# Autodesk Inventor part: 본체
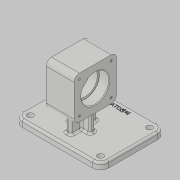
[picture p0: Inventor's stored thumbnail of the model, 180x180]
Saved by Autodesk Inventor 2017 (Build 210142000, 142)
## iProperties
Part Number: 본체
Material: 일반
Document SubType Name: Modeling
Designer: mrc
Density: 1 g/cm^3
Appearance: 기본값
Author: mrc
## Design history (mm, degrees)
sketch "스케치1"
  geometry: L1 (65, -49)-(-65, -49); L2 (-65, -49)-(-65, 49); L3 (-65, 49)-(65, 49); L4 (65, 49)-(65, -49); L5 (65, -49)-(-65, 49); L6 (-65, -49)-(65, 49); 1 further point
  constraints: 12 end point, 2 midpoint, 2 parallel, 1 horizontal, 1 perpendicular
  dimensions: "d1" = 130 distance of L2.end L3.end; "d2" = 98 distance of L1.end L2.end
extrude "돌출1" new body sketch "스케치1" distance "d3" = 10; taper "d4" = 0 deg
sketch "스케치7"
  geometry: L1 (0, -49)-(0, 49) reference; L2 (0, -49)-(10, -49) reference; L3 (10, 49)-(10, -49) reference; L4 (0, 49)-(10, 49) reference; L5 (0, -49)-(0, 13); L6 (0, 13)-(70, 13); L7 (38, -19)-(102, -19); L8 (102, -19)-(102, 45); L9 (102, 45)-(38, 45); L10 (38, 45)-(38, -19); L11 (38, -19)-(102, 45); L12 (102, -19)-(38, 45); 1 further point
  constraints: 16 end point, 2 midpoint, 2 parallel, 2 perpendicular, 1 horizontal, 1 point on line
  dimensions: "d21" = 62 distance of L1.start L5.end; "d22" = 70 distance of L5.end L6.end; "d23" = 64 distance of L9.end L8.end; "d24" = 64 distance of L8.end L7.end
extrude "돌출3" join sketch "스케치7" stored distance "d25" = 42; taper "d26" = 0 deg
sketch "스케치8"
  geometry: L1 (49, 10)-(49, 0) reference; L2 (49, 0)-(-49, 0) reference; L3 (-49, 0)-(-49, 10) reference; L4 (-49, 10)-(49, 10) reference; L5 (19, 38)-(-45, 38) reference; L6 (-45, 38)-(-45, 102) reference; L7 (-45, 102)-(19, 102) reference; L8 (19, 102)-(19, 38) reference; L9 (19, 38)-(19, 102) reference; L10 (19, 102)-(-45, 102) reference; L11 (-45, 102)-(-45, 38) reference; L12 (-45, 38)-(19, 38) reference; C1 r 20.523 at (-13, 70); 1 further point
  constraints: 1 centre point
hole "구멍2" sketch "스케치8" at (-13, 70) diameter "d27" = 36; stored, may be unused: countersink angle "d31" = 90 deg, drill point angle "d33" = 118 deg; dims "d28" = 6, "d29" = 42, "d30" = 15, "d32" = 8
sketch "스케치9"
  geometry: L1 (19, 38)-(19, 102) reference; L2 (19, 102)-(-45, 102) reference; L3 (-45, 102)-(-45, 38) reference; L4 (-45, 38)-(19, 38) reference; L5 (-13, 70)-(-13, 94); L6 (-13, 94)-(-37, 94); C1 r 21 at (-13, 70) reference; C2 r 4.148 at (-37, 94); 1 further point
  constraints: 4 end point, 1 centre point, 1 coincident, 1 perpendicular, 1 vertical
  dimensions: "d34" = 24 distance of L5.start L5.end; "d35" = 24 distance of L5.end L6.end
hole "구멍3" sketch "스케치9" at (-37, 94) diameter "d36" = 3.242; stored, may be unused: countersink angle "d40" = 90 deg, drill point angle "d42" = 118 deg; dims "d37" = 8, "d38" = 42, "d39" = 15, "d41" = 10
fillet "모깎기1" dims "d55" = 8
sketch "스케치11"
  geometry: L1 (4, -33)-(-4, -33); L2 (-4, -33)-(-4, 7); L3 (-4, 7)-(4, 7); L4 (4, 7)-(4, -33); L5 (4, -33)-(-4, 7); L6 (-4, -33)-(4, 7); L7 (17, -17)-(-17, -17); L8 (-17, -17)-(-17, -9); L9 (-17, -9)-(17, -9); L10 (17, -9)-(17, -17); L11 (17, -17)-(-17, -9); L12 (-17, -17)-(17, -9); L13 (65, 49)-(65, -49) reference; L14 (-65, 49)-(65, 49) reference; 3 further points
  constraints: 24 end point, 5 midpoint, 4 parallel, 2 horizontal, 2 perpendicular
  dimensions: "d73" = 34 distance of L8.end L9.end; "d74" = 40 distance of L3.end L1.start; "d75" = 65 distance from line of L13 point (0, -13); "d76" = 62 distance from line of point (0, -13) L14; "d77" = 8 distance of L2.end L3.end; "d78" = 8 distance of L7.end L8.end
extrude "돌출4" join sketch "스케치11" stored distance "d79" = 42; taper "d80" = 0 deg
sketch "스케치12"
  geometry: L1 (-17, -17)-(-17, -9) reference; L2 (-17, -9)-(-4, -9) reference; L3 (-4, -9)-(-4, 7) reference; L4 (-4, 7)-(4, 7) reference; L5 (4, 7)-(4, -9) reference; L6 (4, -9)-(17, -9) reference; L7 (17, -9)-(17, -17) reference; L8 (17, -17)-(4, -17) reference; L9 (4, -17)-(4, -33) reference; L10 (4, -33)-(-4, -33) reference; L11 (-4, -33)-(-4, -17) reference; L12 (-4, -17)-(-17, -17) reference; L13 (65, 49)-(-65, 49) reference; L14 (-65, 49)-(-65, -49) reference; L15 (-65, -49)-(65, -49) reference; L16 (65, -49)-(65, 49) reference; L17 (-65, 49)-(-53, 49); L18 (-53, 49)-(-53, 37); C1 r 7.324 at (-53, 37); 1 further point
  constraints: 4 end point, 1 centre point, 1 coincident, 1 perpendicular, 1 point on line
  dimensions: "d81" = 12 distance of L13.end L17.end; "d82" = 12 distance of L17.end L18.end
hole "구멍4" sketch "스케치12" at (-53, 37) diameter "d83" = 9; stored, may be unused: countersink angle "d87" = 90 deg, drill point angle "d89" = 118 deg; dims "d84" = 8, "d85" = 42, "d86" = 15, "d88" = 10
fillet "모깎기2" dims "d96" = 12
chamfer "모따기1" distance "d97" = 1; stored, may be unused: second distance "d98" = 2, angle "d99" = 45 deg
fillet "모깎기3" dims "d100" = 3
sketch "스케치14"
  geometry: L1 (-53, 49)-(53, 49) reference; L2 (65, 37)-(65, -37) reference; L3 (53, -49)-(-53, -49) reference; L4 (-65, -37)-(-65, 37) reference; L5 (0, 49)-(0, 39); C1 r 4.5 at (53, -37) reference; C2 r 4.5 at (-53, -37) reference; C3 r 4.5 at (53, 37) reference; C4 r 4.5 at (-53, 37) reference; A1 r 12 centre (-53, 37) between (-53, 49) and (-65, 37) reference; A2 r 12 centre (53, 37) between (65, 37) and (53, 49) reference; A3 r 12 centre (53, -37) between (53, -49) and (65, -37) reference; A4 r 12 centre (-53, -37) between (-65, -37) and (-53, -49) reference; 2 further points
  constraints: 2 end point, 1 coincident, 1 midpoint, 1 vertical, 1 other
  dimensions: "d103" = 10 distance of L5.start L5.end
  node "투영된 루프8"
fillet "모깎기5" dims "d104" = 3
feature "엠보싱1" dims "d105" = 0.5, "d106" = 0
fillet "모깎기6" dims "d107" = 0.3
node "솔리드1"
pattern_linear "직사각형 패턴1" dims "d45" = 48, "d48" = 48
mirror "미러2"
mirror "미러3"
pattern_linear "직사각형 패턴2" dims "d51" = 48, "d54" = 48
pattern_linear "직사각형 패턴3" dims "d92" = 106, "d95" = 74
node "투영된 루프2"
node "투영된 루프3"
node "투영된 루프4"
node "투영된 루프6"
node "절단 모서리 투영1"
